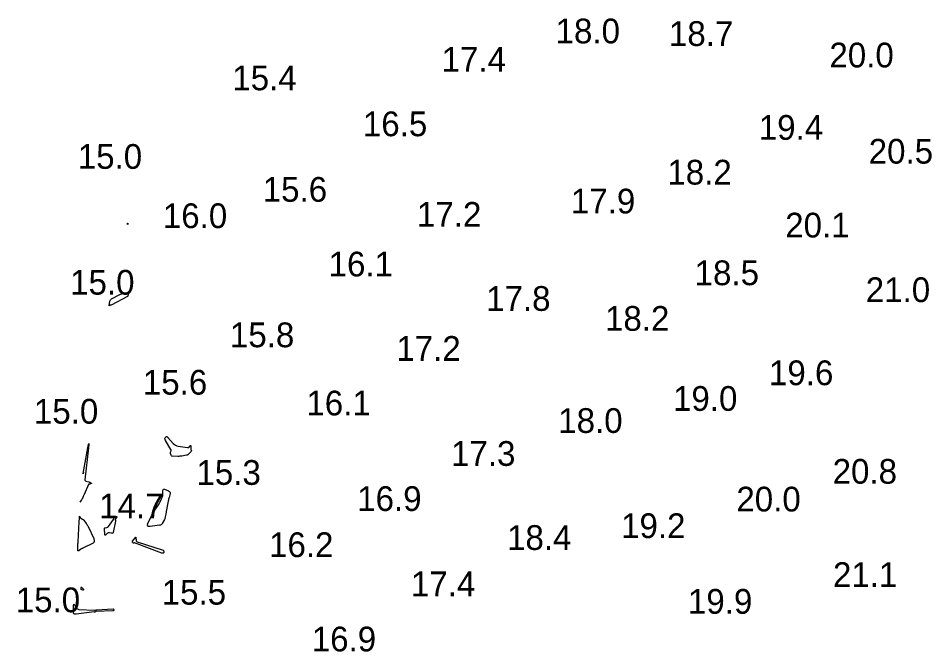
# Model space of a CAD drawing. Extents: x 3040093 to 3056816, y 408076 to 509144.
# Drawn here: x 3044718.9 to 3044903.5, y 434378.3 to 434506.4 of the extents above; entities that cross this region are included whole.
import ezdxf

# ---------------------------------------------------------------- set-up
doc = ezdxf.new("R2010")
doc.units = 0
doc.layers.add('V-CHAN-CONT-EL15', color=7, linetype='Continuous')
doc.layers.add('V-TOPO-SOUN-0810', color=7, linetype='Continuous')

msp = doc.modelspace()

# ---------------------------------------------------------------- linework, layer by layer
at = {"layer": 'V-CHAN-CONT-EL15'}
for points in [[(3044741.12, 434464.79), (3044741.12, 434464.78), (3044741.11, 434464.76), (3044741.1, 434464.75), (3044741.02, 434464.7), (3044741, 434464.69), (3044740.99, 434464.7), (3044740.99, 434464.71), (3044740.99, 434464.72), (3044741.03, 434464.95), (3044741.04, 434464.98), (3044741.05, 434464.99), (3044741.06, 434464.98), (3044741.07, 434464.96), (3044741.12, 434464.81)], [(3044741.08, 434450.24), (3044741.06, 434450.21), (3044741.04, 434450.18), (3044741, 434450.16), (3044737.69, 434448.42), (3044737.67, 434448.41), (3044737.64, 434448.4), (3044737.62, 434448.4), (3044737.6, 434448.39), (3044737.5, 434448.39), (3044737.48, 434448.38), (3044737.46, 434448.38), (3044737.44, 434448.36), (3044737.42, 434448.35), (3044737.33, 434448.25), (3044737.31, 434448.23), (3044737.3, 434448.23), (3044737.29, 434448.24), (3044737.29, 434448.26), (3044737.46, 434449.2), (3044737.5, 434449.36), (3044737.57, 434449.49), (3044737.68, 434449.6), (3044737.81, 434449.69), (3044739.46, 434450.55), (3044739.59, 434450.61), (3044739.73, 434450.66), (3044739.87, 434450.7), (3044740.02, 434450.72), (3044740.86, 434450.79), (3044740.89, 434450.79), (3044740.92, 434450.78), (3044740.95, 434450.77), (3044740.98, 434450.76), (3044741.12, 434450.67), (3044741.13, 434450.66), (3044741.14, 434450.65), (3044741.15, 434450.63), (3044741.15, 434450.62), (3044741.15, 434450.55), (3044741.15, 434450.53), (3044741.15, 434450.51), (3044741.14, 434450.49), (3044741.14, 434450.48), (3044741.09, 434450.27)], [(3044753.79, 434419.22), (3044753.8, 434419.19), (3044753.82, 434419.16), (3044753.84, 434419.13), (3044753.95, 434419.03), (3044753.97, 434419), (3044753.98, 434418.98), (3044753.97, 434418.95), (3044753.96, 434418.92), (3044753.85, 434418.79), (3044753.83, 434418.76), (3044753.8, 434418.73), (3044753.77, 434418.7), (3044753.75, 434418.67), (3044753.33, 434418.25), (3044753.25, 434418.17), (3044753.16, 434418.12), (3044753.06, 434418.07), (3044752.95, 434418.05), (3044751.99, 434417.89), (3044751.79, 434417.86), (3044751.59, 434417.84), (3044751.4, 434417.83), (3044751.2, 434417.83), (3044750.06, 434417.87), (3044749.98, 434417.88), (3044749.92, 434417.91), (3044749.87, 434417.97), (3044749.83, 434418.04), (3044749.71, 434418.41), (3044749.7, 434418.48), (3044749.69, 434418.55), (3044749.7, 434418.62), (3044749.72, 434418.69), (3044749.82, 434418.97), (3044749.84, 434419.04), (3044749.84, 434419.11), (3044749.83, 434419.17), (3044749.79, 434419.24), (3044748.68, 434421.07), (3044748.66, 434421.11), (3044748.64, 434421.15), (3044748.62, 434421.19), (3044748.6, 434421.23), (3044748.53, 434421.39), (3044748.51, 434421.43), (3044748.51, 434421.46), (3044748.53, 434421.5), (3044748.55, 434421.53), (3044748.82, 434421.81), (3044748.85, 434421.83), (3044748.87, 434421.83), (3044748.9, 434421.83), (3044748.93, 434421.82), (3044749.05, 434421.75), (3044749.08, 434421.74), (3044749.11, 434421.72), (3044749.13, 434421.69), (3044749.16, 434421.67), (3044750.27, 434420.42), (3044750.48, 434420.22), (3044750.71, 434420.07), (3044750.96, 434419.96), (3044751.23, 434419.89), (3044753.14, 434419.59), (3044753.23, 434419.59), (3044753.31, 434419.6), (3044753.38, 434419.64), (3044753.44, 434419.7), (3044753.69, 434419.99), (3044753.74, 434420.04), (3044753.78, 434420.05), (3044753.8, 434420.02), (3044753.8, 434419.94), (3044753.79, 434419.26)], [(3044748.83, 434406.56), (3044748.8, 434406.43), (3044748.78, 434406.29), (3044748.75, 434406.15), (3044748.65, 434405.6), (3044748.62, 434405.47), (3044748.58, 434405.34), (3044748.53, 434405.21), (3044748.47, 434405.08), (3044748.05, 434404.28), (3044747.94, 434404.13), (3044747.81, 434404.01), (3044747.66, 434403.93), (3044747.48, 434403.89), (3044745.57, 434403.65), (3044745.26, 434403.65), (3044745.09, 434403.75), (3044745.04, 434403.95), (3044745.14, 434404.25), (3044745.85, 434405.79), (3044745.98, 434406.04), (3044746.11, 434406.3), (3044746.26, 434406.54), (3044746.42, 434406.78), (3044747.14, 434407.82), (3044747.26, 434408.02), (3044747.38, 434408.21), (3044747.49, 434408.42), (3044747.59, 434408.63), (3044748.01, 434409.57), (3044748.07, 434409.73), (3044748.12, 434409.9), (3044748.15, 434410.07), (3044748.16, 434410.24), (3044748.17, 434410.94), (3044748.19, 434411.09), (3044748.26, 434411.17), (3044748.36, 434411.2), (3044748.51, 434411.17), (3044749.33, 434410.85), (3044749.49, 434410.76), (3044749.59, 434410.64), (3044749.62, 434410.5), (3044749.6, 434410.32), (3044749.41, 434409.54), (3044749.36, 434409.35), (3044749.31, 434409.16), (3044749.27, 434408.96), (3044749.23, 434408.77), (3044748.85, 434406.7)], [(3044731.1, 434398.71), (3044731.04, 434398.71), (3044731, 434398.76), (3044730.99, 434398.86), (3044731, 434399.77), (3044731.01, 434399.96), (3044731.01, 434400.15), (3044731.02, 434400.35), (3044731.03, 434400.54), (3044731.18, 434403.27), (3044731.2, 434403.52), (3044731.21, 434403.78), (3044731.22, 434404.03), (3044731.23, 434404.28), (3044731.29, 434405.69), (3044731.3, 434405.73), (3044731.31, 434405.75), (3044731.33, 434405.74), (3044731.35, 434405.7), (3044731.46, 434405.49), (3044731.49, 434405.43), (3044731.52, 434405.39), (3044731.57, 434405.35), (3044731.61, 434405.32), (3044731.92, 434405.14), (3044731.99, 434405.09), (3044732.05, 434405.05), (3044732.11, 434404.99), (3044732.16, 434404.93), (3044732.69, 434404.24), (3044732.79, 434404.1), (3044732.88, 434403.95), (3044732.97, 434403.81), (3044733.04, 434403.65), (3044734.18, 434401.23), (3044734.22, 434401.15), (3044734.24, 434401.07), (3044734.25, 434400.98), (3044734.26, 434400.89), (3044734.25, 434400.54), (3044734.24, 434400.46), (3044734.21, 434400.39), (3044734.16, 434400.33), (3044734.09, 434400.28), (3044732.01, 434399.29), (3044731.9, 434399.24), (3044731.79, 434399.18), (3044731.69, 434399.11), (3044731.59, 434399.04), (3044731.19, 434398.76)], [(3044738.57, 434405.19), (3044738.55, 434405.15), (3044738.55, 434405.11), (3044738.55, 434405.06), (3044738.56, 434404.89), (3044738.57, 434404.84), (3044738.57, 434404.8), (3044738.56, 434404.75), (3044738.56, 434404.71), (3044738.11, 434402.46), (3044738.08, 434402.36), (3044738.02, 434402.3), (3044737.94, 434402.27), (3044737.84, 434402.28), (3044737.39, 434402.38), (3044737.28, 434402.39), (3044737.18, 434402.38), (3044737.08, 434402.35), (3044736.99, 434402.29), (3044736.62, 434401.98), (3044736.54, 434401.93), (3044736.48, 434401.93), (3044736.44, 434401.97), (3044736.42, 434402.07), (3044736.36, 434403.19), (3044736.36, 434403.27), (3044736.39, 434403.33), (3044736.44, 434403.37), (3044736.52, 434403.4), (3044736.86, 434403.48), (3044736.94, 434403.5), (3044737.01, 434403.54), (3044737.08, 434403.59), (3044737.14, 434403.66), (3044738.18, 434405.09), (3044738.2, 434405.12), (3044738.21, 434405.15), (3044738.22, 434405.19), (3044738.22, 434405.22), (3044738.21, 434405.36), (3044738.21, 434405.39), (3044738.22, 434405.42), (3044738.24, 434405.44), (3044738.27, 434405.46), (3044738.77, 434405.68), (3044738.84, 434405.7), (3044738.87, 434405.69), (3044738.87, 434405.66), (3044738.84, 434405.6), (3044738.59, 434405.23)], [(3044748.18, 434398.26), (3044748.16, 434398.25), (3044748.14, 434398.24), (3044748.12, 434398.24), (3044748.02, 434398.26), (3044747.99, 434398.26), (3044747.97, 434398.27), (3044747.94, 434398.27), (3044747.92, 434398.28), (3044742.46, 434400.32), (3044742.43, 434400.33), (3044742.41, 434400.33), (3044742.38, 434400.33), (3044742.36, 434400.32), (3044742.26, 434400.29), (3044742.23, 434400.29), (3044742.21, 434400.29), (3044742.19, 434400.3), (3044742.18, 434400.32), (3044742.04, 434400.51), (3044742.02, 434400.54), (3044742.01, 434400.58), (3044742.02, 434400.62), (3044742.04, 434400.66), (3044742.61, 434401.45), (3044742.63, 434401.48), (3044742.65, 434401.48), (3044742.67, 434401.47), (3044742.67, 434401.43), (3044742.7, 434401.26), (3044742.71, 434401.22), (3044742.71, 434401.17), (3044742.72, 434401.13), (3044742.73, 434401.09), (3044742.79, 434400.75), (3044742.81, 434400.69), (3044742.85, 434400.63), (3044742.89, 434400.59), (3044742.96, 434400.56), (3044748.19, 434398.87), (3044748.23, 434398.85), (3044748.26, 434398.83), (3044748.29, 434398.79), (3044748.3, 434398.75), (3044748.35, 434398.57), (3044748.36, 434398.53), (3044748.35, 434398.49), (3044748.34, 434398.46), (3044748.32, 434398.43), (3044748.2, 434398.28)], [(3044732.11, 434390.94), (3044732.11, 434390.92), (3044732.11, 434390.9), (3044732.1, 434390.88), (3044732.04, 434390.79), (3044732.03, 434390.77), (3044732.01, 434390.76), (3044731.99, 434390.76), (3044731.97, 434390.76), (3044731.77, 434390.86), (3044731.73, 434390.88), (3044731.7, 434390.91), (3044731.68, 434390.95), (3044731.67, 434390.99), (3044731.62, 434391.33), (3044731.61, 434391.39), (3044731.63, 434391.41), (3044731.65, 434391.41), (3044731.7, 434391.37), (3044732.09, 434390.96)], [(3044738.09, 434386.63), (3044738.07, 434386.63), (3044738.05, 434386.62), (3044738.03, 434386.62), (3044734.63, 434386.44), (3044734.62, 434386.44), (3044734.61, 434386.44), (3044734.61, 434386.44), (3044734.6, 434386.44), (3044734.56, 434386.42), (3044734.56, 434386.42), (3044734.55, 434386.42), (3044734.54, 434386.41), (3044734.53, 434386.41), (3044734.44, 434386.34), (3044734.42, 434386.33), (3044734.41, 434386.33), (3044734.39, 434386.33), (3044734.37, 434386.34), (3044734.31, 434386.38), (3044734.3, 434386.39), (3044734.28, 434386.4), (3044734.26, 434386.4), (3044734.25, 434386.4), (3044730.61, 434385.94), (3044730.36, 434385.94), (3044730.19, 434386.03), (3044730.09, 434386.19), (3044730.07, 434386.43), (3044730.12, 434387.78), (3044730.14, 434387.91), (3044730.18, 434387.96), (3044730.23, 434387.94), (3044730.31, 434387.83), (3044730.66, 434387.22), (3044730.76, 434387.09), (3044730.88, 434386.99), (3044731.02, 434386.93), (3044731.19, 434386.9), (3044734.37, 434386.72), (3044734.41, 434386.72), (3044734.44, 434386.72), (3044734.48, 434386.73), (3044734.51, 434386.74), (3044734.65, 434386.8), (3044734.68, 434386.81), (3044734.71, 434386.82), (3044734.75, 434386.82), (3044734.78, 434386.83), (3044738.09, 434387), (3044738.11, 434387), (3044738.13, 434386.99), (3044738.15, 434386.98), (3044738.16, 434386.96), (3044738.23, 434386.88), (3044738.24, 434386.86), (3044738.24, 434386.85), (3044738.24, 434386.84), (3044738.25, 434386.83), (3044738.25, 434386.76), (3044738.25, 434386.75), (3044738.25, 434386.74), (3044738.24, 434386.73), (3044738.24, 434386.72), (3044738.23, 434386.69), (3044738.23, 434386.68), (3044738.22, 434386.67), (3044738.21, 434386.67), (3044738.21, 434386.66), (3044738.11, 434386.63)]]:
    msp.add_lwpolyline(points, close=True, dxfattribs=at)
msp.add_lwpolyline([(3044732.09, 434414.56), (3044732.07, 434414.34), (3044732.07, 434414.32), (3044732.07, 434414.31), (3044732.08, 434414.32), (3044732.08, 434414.34), (3044732.99, 434419.57), (3044733.11, 434420.23), (3044733.17, 434420.45), (3044733.17, 434420.22), (3044733.1, 434419.55), (3044732.41, 434413.11), (3044732.41, 434413.01), (3044732.44, 434412.93), (3044732.5, 434412.87), (3044732.59, 434412.83), (3044733.17, 434412.66), (3044733.19, 434412.66), (3044733.21, 434412.65), (3044733.22, 434412.65), (3044733.24, 434412.64), (3044733.31, 434412.62), (3044733.33, 434412.61), (3044733.35, 434412.61), (3044733.36, 434412.6), (3044733.38, 434412.59), (3044733.68, 434412.42), (3044733.72, 434412.39), (3044733.73, 434412.37), (3044733.71, 434412.35), (3044733.67, 434412.33), (3044733.38, 434412.24), (3044733.35, 434412.23), (3044733.33, 434412.23), (3044733.31, 434412.22), (3044733.29, 434412.21), (3044733.2, 434412.19), (3044733.18, 434412.18), (3044733.16, 434412.17), (3044733.14, 434412.16), (3044733.13, 434412.14), (3044732.23, 434410.1), (3044732.19, 434410.01), (3044732.15, 434409.93), (3044732.12, 434409.84), (3044732.08, 434409.75), (3044731.93, 434409.39), (3044731.89, 434409.31), (3044731.85, 434409.22), (3044731.8, 434409.15), (3044731.74, 434409.07), (3044731.36, 434408.6)], dxfattribs=at)

# ---------------------------------------------------------------- texts
at = {"layer": 'V-TOPO-SOUN-0810'}
for s, p in [('18.0 ', (3044827.51, 434501.31)), ('18.7 ', (3044850.41, 434500.79)), ('17.4 ', (3044804.48, 434495.57)), ('20.0 ', (3044882.83, 434496.45)), ('15.4 ', (3044762.19, 434491.83)), ('16.5 ', (3044788.57, 434482.54)), ('19.4 ', (3044868.56, 434481.82)), ('20.5 ', (3044890.77, 434477)), ('15.0 ', (3044730.96, 434475.95)), ('18.2 ', (3044850.09, 434472.77)), ('15.6 ', (3044768.33, 434469.29)), ('17.9 ', (3044830.6, 434466.93)), ('16.0 ', (3044748.15, 434463.97)), ('17.2 ', (3044799.5, 434464.24)), ('20.1 ', (3044873.9, 434462.07)), ('16.1 ', (3044781.65, 434454.2)), ('18.5 ', (3044855.6, 434452.43)), ('15.0 ', (3044729.42, 434450.52)), ('21.0 ', (3044890.18, 434449.01)), ('17.8 ', (3044813.47, 434447.24)), ('18.2 ', (3044837.49, 434443.21)), ('15.8 ', (3044761.7, 434439.89)), ('17.2 ', (3044795.33, 434437.14)), ('19.6 ', (3044870.62, 434432.22)), ('15.6 ', (3044744.11, 434430.31)), ('19.0 ', (3044851.23, 434427.03)), ('16.1 ', (3044777.15, 434426.11)), ('15.0 ', (3044722.1, 434424.44)), ('18.0 ', (3044828.04, 434422.57)), ('17.3 ', (3044806.38, 434415.91)), ('20.8 ', (3044883.48, 434412.3)), ('15.3 ', (3044754.94, 434412.07)), ('16.9 ', (3044787.42, 434406.79)), ('14.7 ', (3044735.29, 434405.31)), ('20.0 ', (3044864.03, 434406.69)), ('19.2 ', (3044840.74, 434401.31)), ('18.4 ', (3044817.7, 434398.92)), ('16.2 ', (3044769.61, 434397.47)), ('21.1 ', (3044883.55, 434391.43)), ('17.4 ', (3044798.28, 434389.56)), ('15.5 ', (3044747.92, 434387.86)), ('15.0 ', (3044718.43, 434386.32)), ('19.9 ', (3044854.25, 434386.02)), ('16.9 ', (3044778.24, 434378.41))]:
    msp.add_text(s, height=5, dxfattribs=at).set_placement(p)

doc.saveas('drawing.dxf')
